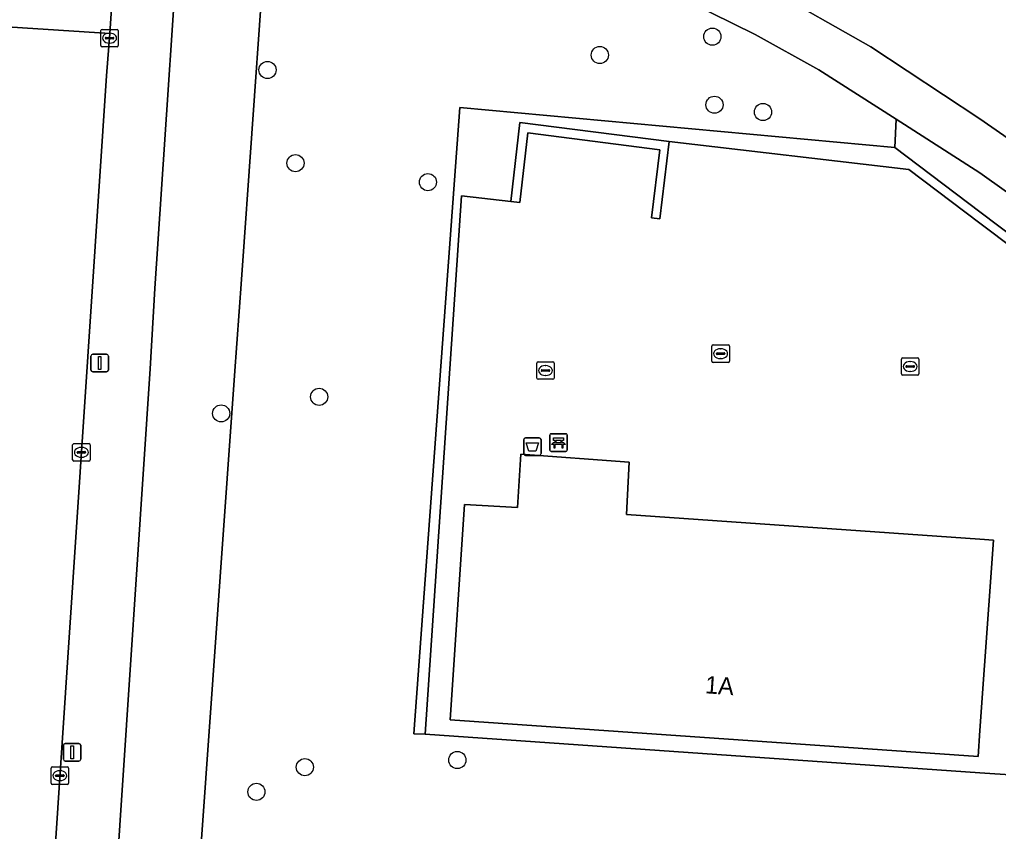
# Model space of a CAD drawing. Extents: x 161848 to 162726, y 385382 to 386521.
# Drawn here: x 162445.2 to 162501.1, y 385534.3 to 385580.7 of the extents above; entities that cross this region are included whole.
import ezdxf

# ---------------------------------------------------------------- set-up
doc = ezdxf.new("R2010")
doc.units = 0
for name, color, linetype in [('IMGEO_Afvalbak', 7, 'Continuous'), ('IMGEO_Bank', 7, 'Continuous'), ('IMGEO_Boom', 7, 'Continuous'), ('IMGEO_Erf', 7, 'Continuous'), ('IMGEO_Groenvoorziening', 7, 'Continuous'), ('IMGEO_Kolk', 7, 'Continuous'), ('IMGEO_Lichtmast', 7, 'Continuous'), ('IMGEO_Muur', 7, 'Continuous'), ('IMGEO_Pand', 7, 'Continuous'), ('IMGEO_Pand_nummerreeks', 7, 'Continuous'), ('IMGEO_Rijbaan_lokaal_gesloten', 7, 'Continuous'), ('IMGEO_Rijbaan_lokaal_open', 7, 'Continuous'), ('IMGEO_Voetpad_halfverhard', 7, 'Continuous'), ('IMGEO_Voetpad_open', 7, 'Continuous')]:
    doc.layers.add(name, color=color, linetype=linetype)

msp = doc.modelspace()

# ---------------------------------------------------------------- linework, layer by layer
at = {"layer": 'IMGEO_Afvalbak'}
for p, q in [((162473.969, 385555.901), (162473.969, 385556.701)), ((162473.969, 385556.701), (162473.969, 385555.901)), ((162474.069, 385556.801), (162474.859, 385556.801)), ((162474.859, 385556.801), (162474.069, 385556.801)), ((162474.959, 385556.701), (162474.959, 385555.901)), ((162474.959, 385555.901), (162474.959, 385556.701)), ((162474.859, 385555.801), (162474.069, 385555.801)), ((162474.069, 385555.801), (162474.859, 385555.801))]:
    msp.add_line(p, q, dxfattribs=at)
msp.add_lwpolyline([(162474.112, 385556.515), (162474.816, 385556.515), (162474.667, 385556.045), (162474.261, 385556.045), (162474.112, 385556.515)], dxfattribs=at)
for centre, start, end in [((162474.069, 385556.701), 90, 180), ((162474.069, 385556.701), 90, 180), ((162474.859, 385556.701), 0, 90), ((162474.859, 385556.701), 360, 90), ((162474.069, 385555.901), 180, 270), ((162474.069, 385555.901), 180, 270), ((162474.859, 385555.901), 270, 0), ((162474.859, 385555.901), 270, 0)]:
    msp.add_arc(centre, 0.1, start, end, dxfattribs=at)
at = {"layer": 'IMGEO_Bank'}
for p, q in [((162475.455, 385556.109), (162475.455, 385556.95)), ((162475.455, 385556.95), (162475.455, 385556.109)), ((162475.53, 385557.034), (162476.371, 385557.034)), ((162476.371, 385557.034), (162475.53, 385557.034)), ((162476.455, 385556.959), (162476.455, 385556.118)), ((162476.455, 385556.118), (162476.455, 385556.959)), ((162476.152, 385556.432), (162475.759, 385556.432)), ((162475.764, 385556.54), (162475.764, 385556.646)), ((162475.808, 385556.646), (162475.808, 385556.54)), ((162476.096, 385556.652), (162475.814, 385556.652)), ((162475.814, 385556.534), (162476.096, 385556.534)), ((162476.102, 385556.54), (162476.102, 385556.646)), ((162476.146, 385556.646), (162476.146, 385556.54)), ((162476.38, 385556.034), (162475.539, 385556.034)), ((162475.539, 385556.034), (162476.38, 385556.034))]:
    msp.add_line(p, q, dxfattribs=at)
for points in [[(162475.702, 385556.432), (162475.56, 385556.432), (162475.672, 385556.534), (162475.758, 385556.534)], [(162475.758, 385556.652), (162475.672, 385556.652), (162475.672, 385556.813), (162476.235, 385556.813), (162476.235, 385556.652), (162476.152, 385556.652)], [(162475.752, 385556.425), (162475.752, 385556.218), (162475.709, 385556.218), (162475.709, 385556.425)], [(162476.152, 385556.534), (162476.235, 385556.534), (162476.347, 385556.432), (162476.208, 385556.432)], [(162476.202, 385556.425), (162476.202, 385556.218), (162476.158, 385556.218), (162476.158, 385556.425)]]:
    msp.add_lwpolyline(points, dxfattribs=at)
for centre, radius, start, end in [((162475.533, 385556.956), 0.0779, 92.4484, 184.2845), ((162475.533, 385556.956), 0.0779, 92.4484, 184.2845), ((162476.377, 385556.956), 0.0779, 2.4484, 94.2845), ((162476.377, 385556.956), 0.0779, 2.4484, 94.2845), ((162475.702, 385556.425), 0.00671, 2.8957, 87.1043), ((162475.759, 385556.425), 0.00671, 92.8957, 177.1043), ((162475.757, 385556.645), 0.00671, 2.8957, 87.1043), ((162475.757, 385556.541), 0.00671, 272.8957, 357.1043), ((162475.814, 385556.645), 0.00671, 92.8957, 177.1043), ((162475.814, 385556.541), 0.00671, 182.8957, 267.1043), ((162476.096, 385556.645), 0.00671, 2.8957, 87.1043), ((162476.096, 385556.541), 0.00671, 272.8957, 357.1043), ((162476.153, 385556.645), 0.00671, 92.8957, 177.1043), ((162476.153, 385556.541), 0.00671, 182.8957, 267.1043), ((162476.151, 385556.425), 0.00671, 2.8957, 87.1043), ((162476.208, 385556.425), 0.00671, 92.8957, 177.1043), ((162475.533, 385556.112), 0.0779, 182.4484, 274.2845), ((162475.533, 385556.112), 0.0779, 182.4484, 274.2845), ((162476.377, 385556.112), 0.0779, 272.4484, 4.2845), ((162476.377, 385556.112), 0.0779, 272.4484, 4.2845)]:
    msp.add_arc(centre, radius, start, end, dxfattribs=at)
at = {"layer": 'IMGEO_Boom'}
for centre in [(162484.733, 385579.702), (162478.31, 385578.652), (162459.354, 385577.8), (162484.852, 385575.816), (162487.621, 385575.4), (162460.947, 385572.481), (162468.504, 385571.399), (162462.297, 385559.146), (162456.711, 385558.199), (162461.485, 385538.01), (162470.182, 385538.416), (162458.719, 385536.597)]:
    msp.add_circle(centre, 0.489, dxfattribs=at)
at = {"layer": 'IMGEO_Erf'}
for points in [[(162514.355, 385558.257), (162500, 385569.063), (162495.945, 385572.115), (162482.269, 385573.711), (162481.733, 385569.299), (162481.251, 385569.355), (162481.738, 385573.234), (162474.208, 385574.206), (162473.75, 385570.233), (162473.235, 385570.298), (162470.42, 385570.607), (162468.348, 385539.899), (162500, 385537.687), (162517.253, 385536.548), (162519.465, 385536.436), (162519.453, 385536.254), (162527.852, 385535.679), (162529.486, 385535.512), (162532.816, 385540.973), (162532.399, 385541.463), (162532.267, 385541.564), (162523.898, 385547.988)], [(162500, 385551.023), (162500.764, 385550.97), (162500, 385540.105), (162499.895, 385538.612), (162469.765, 385540.716), (162470.593, 385553.008), (162473.621, 385552.819), (162473.807, 385555.866), (162479.989, 385555.423), (162479.835, 385552.43)]]:
    msp.add_lwpolyline(points, close=True, dxfattribs=at)
at = {"layer": 'IMGEO_Groenvoorziening'}
for points in [[(162538.336, 385536.905), (162542.165, 385533.965), (162550.631, 385529.653), (162550.849, 385530.067), (162553.164, 385534.631), (162561.257, 385550.045), (162560.63, 385550.448), (162542.29, 385562.253), (162548.505, 385577.924), (162536.104, 385581.739), (162500, 385593.238), (162479.406, 385599.797), (162476.971, 385587.253), (162484.254, 385584.283), (162487.85, 385582.497), (162493.782, 385579.117), (162500, 385575.013), (162507.332, 385569.904), (162515.688, 385563.43)], [(162454.648, 385591.147), (162452.933, 385565.323), (162452.649, 385560.747), (162450.744, 385531.817), (162455.419, 385531.5), (162457.472, 385560.354), (162457.863, 385565.85), (162459.643, 385590.86), (162456.232, 385592.147)], [(162535.739, 385532.489), (162530.442, 385535.198), (162529.486, 385535.512), (162527.852, 385535.679), (162519.453, 385536.254), (162519.465, 385536.436), (162517.253, 385536.548), (162500, 385537.687), (162468.348, 385539.899), (162467.702, 385539.907), (162470.326, 385575.657), (162495.135, 385573.373), (162495.217, 385574.984), (162490.808, 385577.806), (162487.175, 385579.819), (162483.437, 385581.678), (162479.604, 385583.332), (162459.643, 385590.86), (162457.863, 385565.85), (162457.472, 385560.354), (162455.419, 385531.5)], [(162514.873, 385560.752), (162505.669, 385567.877), (162500, 385571.923), (162495.217, 385574.984), (162495.135, 385573.373), (162500, 385569.702), (162514.642, 385558.655), (162524.216, 385548.303), (162530.769, 385543.318), (162520.722, 385555.082)]]:
    msp.add_lwpolyline(points, dxfattribs=at)
msp.add_lwpolyline([(162470.326, 385575.657), (162467.702, 385539.907), (162468.348, 385539.899), (162470.42, 385570.607), (162473.235, 385570.298), (162473.757, 385574.81), (162482.269, 385573.711), (162495.945, 385572.115), (162500, 385569.063), (162514.355, 385558.257), (162523.898, 385547.988), (162532.267, 385541.564), (162530.769, 385543.318), (162524.216, 385548.303), (162514.642, 385558.655), (162500, 385569.702), (162495.135, 385573.373)], close=True, dxfattribs=at)
at = {"layer": 'IMGEO_Kolk'}
for p, q in [((162449.84, 385579.192), (162449.84, 385580.044)), ((162449.915, 385580.118), (162450.767, 385580.118)), ((162450.328, 385579.898), (162450.353, 385579.898)), ((162450.841, 385580.044), (162450.841, 385579.192)), ((162450.099, 385579.612), (162450.099, 385579.624)), ((162450.537, 385579.575), (162450.139, 385579.575)), ((162450.142, 385579.661), (162450.54, 385579.661)), ((162450.351, 385579.338), (162450.326, 385579.338)), ((162450.583, 385579.624), (162450.583, 385579.612)), ((162450.767, 385579.118), (162449.915, 385579.118)), ((162484.703, 385561.182), (162484.703, 385562.034)), ((162484.778, 385562.108), (162485.63, 385562.108)), ((162485.191, 385561.888), (162485.216, 385561.888)), ((162485.704, 385562.034), (162485.704, 385561.182)), ((162484.962, 385561.602), (162484.962, 385561.614)), ((162485.4, 385561.565), (162485.002, 385561.565)), ((162485.005, 385561.651), (162485.403, 385561.651)), ((162485.214, 385561.328), (162485.189, 385561.328)), ((162485.446, 385561.614), (162485.446, 385561.602)), ((162495.592, 385561.374), (162496.444, 385561.374)), ((162474.711, 385560.218), (162474.711, 385561.07)), ((162474.786, 385561.144), (162475.638, 385561.144)), ((162475.199, 385560.924), (162475.224, 385560.924)), ((162475.712, 385561.07), (162475.712, 385560.218)), ((162485.63, 385561.108), (162484.778, 385561.108)), ((162495.517, 385560.448), (162495.517, 385561.3)), ((162495.776, 385560.868), (162495.776, 385560.88)), ((162496.214, 385560.831), (162495.816, 385560.831)), ((162495.819, 385560.917), (162496.217, 385560.917)), ((162496.005, 385561.154), (162496.03, 385561.154)), ((162496.26, 385560.88), (162496.26, 385560.868)), ((162496.518, 385561.3), (162496.518, 385560.448)), ((162474.97, 385560.638), (162474.97, 385560.65)), ((162475.408, 385560.601), (162475.01, 385560.601)), ((162475.013, 385560.687), (162475.411, 385560.687)), ((162475.222, 385560.364), (162475.197, 385560.364)), ((162475.454, 385560.65), (162475.454, 385560.638)), ((162496.444, 385560.374), (162495.592, 385560.374)), ((162496.028, 385560.594), (162496.003, 385560.594)), ((162475.638, 385560.144), (162474.786, 385560.144)), ((162448.234, 385555.548), (162448.234, 385556.4)), ((162448.309, 385556.474), (162449.161, 385556.474)), ((162449.235, 385556.4), (162449.235, 385555.548)), ((162448.493, 385555.968), (162448.493, 385555.98)), ((162448.931, 385555.931), (162448.533, 385555.931)), ((162448.536, 385556.017), (162448.934, 385556.017)), ((162448.722, 385556.254), (162448.747, 385556.254)), ((162448.977, 385555.98), (162448.977, 385555.968)), ((162449.161, 385555.474), (162448.309, 385555.474)), ((162448.745, 385555.694), (162448.72, 385555.694)), ((162447.002, 385537.098), (162447.002, 385537.95)), ((162447.077, 385538.024), (162447.929, 385538.024)), ((162448.003, 385537.95), (162448.003, 385537.098)), ((162447.261, 385537.518), (162447.261, 385537.53)), ((162447.699, 385537.481), (162447.301, 385537.481)), ((162447.304, 385537.567), (162447.702, 385537.567)), ((162447.49, 385537.804), (162447.515, 385537.804)), ((162447.745, 385537.53), (162447.745, 385537.518)), ((162447.929, 385537.024), (162447.077, 385537.024)), ((162447.513, 385537.244), (162447.488, 385537.244))]:
    msp.add_line(p, q, dxfattribs=at)
for points in [[(162449.84, 385579.192), (162449.84, 385580.044)], [(162449.915, 385580.118), (162450.767, 385580.118)], [(162450.841, 385580.044), (162450.841, 385579.192)], [(162450.767, 385579.118), (162449.915, 385579.118)], [(162484.703, 385561.182), (162484.703, 385562.034)], [(162484.778, 385562.108), (162485.63, 385562.108)], [(162485.704, 385562.034), (162485.704, 385561.182)], [(162495.592, 385561.374), (162496.444, 385561.374)], [(162474.711, 385560.218), (162474.711, 385561.07)], [(162474.786, 385561.144), (162475.638, 385561.144)], [(162475.712, 385561.07), (162475.712, 385560.218)], [(162485.63, 385561.108), (162484.778, 385561.108)], [(162495.517, 385560.448), (162495.517, 385561.3)], [(162496.518, 385561.3), (162496.518, 385560.448)], [(162496.444, 385560.374), (162495.592, 385560.374)], [(162475.638, 385560.144), (162474.786, 385560.144)], [(162448.234, 385555.548), (162448.234, 385556.4)], [(162448.309, 385556.474), (162449.161, 385556.474)], [(162449.235, 385556.4), (162449.235, 385555.548)], [(162449.161, 385555.474), (162448.309, 385555.474)], [(162447.002, 385537.098), (162447.002, 385537.95)], [(162447.077, 385538.024), (162447.929, 385538.024)], [(162448.003, 385537.95), (162448.003, 385537.098)], [(162447.929, 385537.024), (162447.077, 385537.024)]]:
    msp.add_lwpolyline(points, dxfattribs=at)
for centre, radius, start, end in [((162449.917, 385580.042), 0.0765, 91.552, 178.448), ((162449.917, 385580.042), 0.0765, 91.552, 178.448), ((162450.765, 385580.042), 0.0765, 1.552, 88.448), ((162450.765, 385580.042), 0.0765, 1.552, 88.448), ((162449.917, 385579.194), 0.0765, 181.552, 268.448), ((162449.917, 385579.194), 0.0765, 181.552, 268.448), ((162450.139, 385579.621), 0.0403, 85.8775, 175.7526), ((162450.136, 385579.611), 0.0366, 178.938, 274.7102), ((162450.54, 385579.618), 0.043, 264.8664, 352.4533), ((162450.544, 385579.623), 0.0386, 1.7309, 96.639), ((162450.765, 385579.194), 0.0765, 271.552, 358.448), ((162450.765, 385579.194), 0.0765, 271.552, 358.448), ((162484.78, 385562.032), 0.0765, 91.552, 178.448), ((162484.78, 385562.032), 0.0765, 91.552, 178.448), ((162485.628, 385562.032), 0.0765, 1.552, 88.448), ((162485.628, 385562.032), 0.0765, 1.552, 88.448), ((162485.002, 385561.611), 0.0403, 85.8775, 175.7526), ((162484.999, 385561.601), 0.0366, 178.938, 274.7102), ((162485.403, 385561.608), 0.043, 264.8664, 352.4533), ((162485.407, 385561.613), 0.0386, 1.7309, 96.639), ((162495.594, 385561.298), 0.0765, 91.552, 178.448), ((162495.594, 385561.298), 0.0765, 91.552, 178.448), ((162496.442, 385561.298), 0.0765, 1.552, 88.448), ((162496.442, 385561.298), 0.0765, 1.552, 88.448), ((162474.788, 385561.068), 0.0765, 91.552, 178.448), ((162474.788, 385561.068), 0.0765, 91.552, 178.448), ((162475.636, 385561.068), 0.0765, 1.552, 88.448), ((162475.636, 385561.068), 0.0765, 1.552, 88.448), ((162484.78, 385561.184), 0.0765, 181.552, 268.448), ((162484.78, 385561.184), 0.0765, 181.552, 268.448), ((162485.628, 385561.184), 0.0765, 271.552, 358.448), ((162485.628, 385561.184), 0.0765, 271.552, 358.448), ((162495.816, 385560.877), 0.0403, 85.8775, 175.7526), ((162495.813, 385560.867), 0.0366, 178.938, 274.7102), ((162496.217, 385560.874), 0.043, 264.8664, 352.4533), ((162496.221, 385560.879), 0.0386, 1.7309, 96.639), ((162474.788, 385560.22), 0.0765, 181.552, 268.448), ((162474.788, 385560.22), 0.0765, 181.552, 268.448), ((162475.01, 385560.647), 0.0403, 85.8775, 175.7526), ((162475.007, 385560.637), 0.0366, 178.938, 274.7102), ((162475.411, 385560.644), 0.043, 264.8664, 352.4533), ((162475.415, 385560.649), 0.0386, 1.7309, 96.639), ((162475.636, 385560.22), 0.0765, 271.552, 358.448), ((162475.636, 385560.22), 0.0765, 271.552, 358.448), ((162495.594, 385560.45), 0.0765, 181.552, 268.448), ((162495.594, 385560.45), 0.0765, 181.552, 268.448), ((162496.442, 385560.45), 0.0765, 271.552, 358.448), ((162496.442, 385560.45), 0.0765, 271.552, 358.448), ((162448.311, 385556.398), 0.0765, 91.552, 178.448), ((162448.311, 385556.398), 0.0765, 91.552, 178.448), ((162449.159, 385556.398), 0.0765, 1.552, 88.448), ((162449.159, 385556.398), 0.0765, 1.552, 88.448), ((162448.533, 385555.977), 0.0403, 85.8775, 175.7526), ((162448.53, 385555.967), 0.0366, 178.938, 274.7102), ((162448.934, 385555.974), 0.043, 264.8664, 352.4533), ((162448.938, 385555.979), 0.0386, 1.7309, 96.639), ((162448.311, 385555.55), 0.0765, 181.552, 268.448), ((162448.311, 385555.55), 0.0765, 181.552, 268.448), ((162449.159, 385555.55), 0.0765, 271.552, 358.448), ((162449.159, 385555.55), 0.0765, 271.552, 358.448), ((162447.079, 385537.948), 0.0765, 91.552, 178.448), ((162447.079, 385537.948), 0.0765, 91.552, 178.448), ((162447.927, 385537.948), 0.0765, 1.552, 88.448), ((162447.927, 385537.948), 0.0765, 1.552, 88.448), ((162447.301, 385537.527), 0.0403, 85.8775, 175.7526), ((162447.298, 385537.517), 0.0366, 178.938, 274.7102), ((162447.702, 385537.524), 0.043, 264.8664, 352.4533), ((162447.706, 385537.529), 0.0386, 1.7309, 96.639), ((162447.079, 385537.1), 0.0765, 181.552, 268.448), ((162447.079, 385537.1), 0.0765, 181.552, 268.448), ((162447.927, 385537.1), 0.0765, 271.552, 358.448), ((162447.927, 385537.1), 0.0765, 271.552, 358.448)]:
    msp.add_arc(centre, radius, start, end, dxfattribs=at)
for centre, major_axis, ratio, start_param, end_param in [((162450.327, 385579.618), (-0.387, 0.002), 0.722429, 4.712389, 7.853982), ((162450.352, 385579.618), (-0.39, 0.002), 0.717154, 1.570796, 4.712389), ((162485.19, 385561.608), (-0.387, 0.002), 0.722429, 4.712389, 7.853982), ((162485.215, 385561.608), (-0.39, 0.002), 0.717154, 1.570796, 4.712389), ((162475.198, 385560.644), (-0.387, 0.002), 0.722429, 4.712389, 7.853982), ((162475.223, 385560.644), (-0.39, 0.002), 0.717154, 1.570796, 4.712389), ((162496.004, 385560.874), (-0.387, 0.002), 0.722429, 4.712389, 7.853982), ((162496.029, 385560.874), (-0.39, 0.002), 0.717154, 1.570796, 4.712389), ((162448.721, 385555.974), (-0.387, 0.002), 0.722429, 4.712389, 7.853982), ((162448.746, 385555.974), (-0.39, 0.002), 0.717154, 1.570796, 4.712389), ((162447.489, 385537.524), (-0.387, 0.002), 0.722429, 4.712389, 7.853982), ((162447.514, 385537.524), (-0.39, 0.002), 0.717154, 1.570796, 4.712389)]:
    msp.add_ellipse(centre, major_axis=major_axis, ratio=ratio, start_param=start_param, end_param=end_param, dxfattribs=at)
at = {"layer": 'IMGEO_Lichtmast'}
for p, q in [((162449.282, 385560.672), (162449.282, 385561.472)), ((162449.282, 385561.472), (162449.282, 385560.672)), ((162449.382, 385561.572), (162450.172, 385561.572)), ((162450.172, 385561.572), (162449.382, 385561.572)), ((162450.272, 385561.472), (162450.272, 385560.672)), ((162450.272, 385560.672), (162450.272, 385561.472)), ((162450.172, 385560.572), (162449.382, 385560.572)), ((162449.382, 385560.572), (162450.172, 385560.572)), ((162447.706, 385538.457), (162447.706, 385539.257)), ((162447.706, 385539.257), (162447.706, 385538.457)), ((162447.806, 385539.357), (162448.596, 385539.357)), ((162448.596, 385539.357), (162447.806, 385539.357)), ((162448.696, 385539.257), (162448.696, 385538.457)), ((162448.696, 385538.457), (162448.696, 385539.257)), ((162448.596, 385538.357), (162447.806, 385538.357)), ((162447.806, 385538.357), (162448.596, 385538.357))]:
    msp.add_line(p, q, dxfattribs=at)
for points in [[(162449.702, 385561.447), (162449.852, 385561.447), (162449.852, 385560.697), (162449.702, 385560.697), (162449.702, 385561.447)], [(162448.126, 385539.232), (162448.276, 385539.232), (162448.276, 385538.482), (162448.126, 385538.482), (162448.126, 385539.232)]]:
    msp.add_lwpolyline(points, dxfattribs=at)
for centre, start, end in [((162449.382, 385561.472), 90, 180), ((162449.382, 385561.472), 90, 180), ((162450.172, 385561.472), 0, 90), ((162450.172, 385561.472), 360, 90), ((162449.382, 385560.672), 180, 270), ((162449.382, 385560.672), 180, 270), ((162450.172, 385560.672), 270, 0), ((162450.172, 385560.672), 270, 0), ((162447.806, 385539.257), 90, 180), ((162447.806, 385539.257), 90, 180), ((162448.596, 385539.257), 0, 90), ((162448.596, 385539.257), 360, 90), ((162447.806, 385538.457), 180, 270), ((162447.806, 385538.457), 180, 270), ((162448.596, 385538.457), 270, 0), ((162448.596, 385538.457), 270, 0)]:
    msp.add_arc(centre, 0.1, start, end, dxfattribs=at)
at = {"layer": 'IMGEO_Muur'}
msp.add_lwpolyline([(162474.208, 385574.206), (162481.738, 385573.234), (162481.251, 385569.355), (162481.733, 385569.299), (162482.269, 385573.711), (162473.757, 385574.81), (162473.235, 385570.298), (162473.75, 385570.233)], close=True, dxfattribs=at)
at = {"layer": 'IMGEO_Pand'}
msp.add_lwpolyline([(162500.764, 385550.97), (162500, 385551.023), (162479.835, 385552.43), (162479.989, 385555.423), (162473.807, 385555.866), (162473.621, 385552.819), (162470.593, 385553.008), (162469.765, 385540.716), (162499.895, 385538.612), (162500, 385540.105)], close=True, dxfattribs=at)
at = {"layer": 'IMGEO_Rijbaan_lokaal_gesloten'}
for points in [[(162450.162, 385577.468), (162450.352, 385579.883), (162442.418, 385580.396), (162442.248, 385577.631), (162439.944, 385543.379), (162439.699, 385539.748), (162437.017, 385500), (162434.834, 385467.105), (162434.805, 385466.668), (162433.595, 385448.457), (162433.536, 385447.496), (162432.367, 385428.377), (162432.18, 385425.321), (162430.698, 385404.895), (162430.353, 385400.004), (162435.988, 385399.644), (162436.331, 385400.107), (162438.143, 385401.743)], [(162442.399, 385460.482), (162442.465, 385461.839), (162450.162, 385577.468)]]:
    msp.add_lwpolyline(points, dxfattribs=at)
at = {"layer": 'IMGEO_Rijbaan_lokaal_open'}
msp.add_lwpolyline([(162442.418, 385580.396), (162450.352, 385579.883), (162451.635, 385598.888)], dxfattribs=at)
at = {"layer": 'IMGEO_Voetpad_halfverhard'}
for points in [[(162515.688, 385563.43), (162507.332, 385569.904), (162500, 385575.013), (162493.782, 385579.117), (162487.85, 385582.497), (162484.254, 385584.283), (162476.971, 385587.253), (162456.716, 385594.689)], [(162456.232, 385592.147), (162459.643, 385590.86), (162479.604, 385583.332), (162483.437, 385581.678), (162487.175, 385579.819), (162490.808, 385577.806), (162495.217, 385574.984), (162500, 385571.923), (162505.669, 385567.877), (162514.873, 385560.752)]]:
    msp.add_lwpolyline(points, dxfattribs=at)
at = {"layer": 'IMGEO_Voetpad_open'}
msp.add_lwpolyline([(162442.256, 385407.756), (162443.737, 385429.387), (162445.688, 385458.726), (162445.849, 385461.151), (162446.446, 385469.756), (162446.676, 385473.196), (162448.539, 385500), (162450.031, 385521.458), (162450.405, 385526.588), (162450.744, 385531.817), (162452.649, 385560.747), (162452.933, 385565.323), (162454.648, 385591.147), (162455.021, 385596.06), (162455.065, 385596.685), (162455.738, 385606.152), (162455.776, 385606.687), (162452.208, 385607.27), (162451.787, 385601.362), (162451.635, 385598.888), (162450.352, 385579.883), (162450.162, 385577.468), (162442.465, 385461.839), (162442.399, 385460.482)], dxfattribs=at)

# ---------------------------------------------------------------- texts
at = {"layer": 'IMGEO_Pand_nummerreeks'}
msp.add_text('1A', height=1, rotation=356.0065, dxfattribs=at).set_placement((162484.294, 385542.228))

doc.saveas('drawing.dxf')
